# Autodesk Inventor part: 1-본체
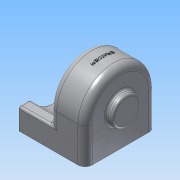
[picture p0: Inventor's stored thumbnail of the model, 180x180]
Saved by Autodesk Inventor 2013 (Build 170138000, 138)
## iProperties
Created: 2015-02
Part Number: 1-본체
Material: 알루미늄 6061
Document SubType Name: Modeling
Designer: Administrator
Density: 2.71 g/cm^3
Mass: 575.526 g
Surface Area: 706.56 cm^2
Volume: 212.371 cm^3
Author: Administrator
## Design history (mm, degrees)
sketch "스케치1"
  geometry: L1 (0, 0)-(50, 0); L2 (50, 0)-(50, 100); L3 (50, 100)-(0, 100); L4 (0, 100)-(0, 0)
  constraints: 8 end point, 2 parallel, 1 horizontal, 1 perpendicular
  dimensions: "d0" = 50 distance of L2.end L3.end; "d2" = 100 distance of L1.end L2.end
extrude "돌출1" new body sketch "스케치1" distance "d3" = 100; taper "d4" = 0 deg
fillet "모깎기1" dims "d5" = 50
fillet "모깎기2" dims "d6" = 10
feature "쉘1" dims "d7" = 4
node "작업 평면2"
sketch "스케치5"
  geometry: L1 (-80, 0)-(0, 0) reference; L2 (-5.359, 30)-(10, 30); L3 (10, 30)-(10, 0); L4 (-90, 50)-(-90, 0) reference; L5 (-80, 0)-(-90, 0) reference; L6 (10, 0)-(0, 0) reference; L7 (-74.641, 30)-(-90, 30); A1 r 40 centre (-40, 50) between (-5.359, 30) and (-74.641, 30); 1 further point
  constraints: 6 end point, 2 parallel, 2 point on circle, 1 centre point, 1 collinear, 1 midpoint, 1 perpendicular, 1 point on line, 1 vertical alignment
  dimensions: "d16" = 40 radius of A1; "d19" = 50 distance from line of L1 A1.centre; "d20" = 30 distance between parallel lines of L6 L2
extrude "돌출3" join sketch "스케치5" stored distance "d21" = 49; taper "d22" = 0 deg
sketch "스케치6"
  geometry: C1 r 25 at (0, 0); A1 r 40 centre (0, 0) between (0, -40) and (0, 40) reference; 1 further point
  constraints: 1 centre point, 1 coincident
  dimensions: "d23" = 50 diameter of C1
extrude "돌출4" join sketch "스케치6" distance "d25" = 10; taper "d26" = -20 deg
sketch "스케치7"
  geometry: C1 r 20 at (0, 0); A1 r 40 centre (0, 0) between (0, 40) and (0, -40) reference; 1 further point
  constraints: 1 centre point, 1 coincident
  dimensions: "d27" = 40 diameter of C1
extrude "돌출5" join sketch "스케치7" distance "d29" = 9; taper "d30" = 0 deg
hole "구멍1" diameter "d33" = 20; stored, may be unused: countersink angle "d37" = 90 deg, drill point angle "d39" = 0 deg; dims "d31" = 10, "d32" = 10, "d34" = 6, "d35" = 28, "d36" = 10, "d38" = 14
hole "구멍2" diameter "d42" = 20; stored, may be unused: countersink angle "d46" = 90 deg, drill point angle "d48" = 0 deg; dims "d40" = 10, "d41" = 10, "d43" = 6, "d44" = 28, "d45" = 8, "d47" = 10
sketch "스케치8"
  geometry: C1 r 14 at (0, 0) reference; C2 r 21.36 at (0, 0) reference; A1 r 18 centre (0, 0) between (-18, 0) and (18, 0); 3 further points
  constraints: 4 point on circle, 2 horizontal alignment, 2 vertical alignment, 1 centre point, 1 coincident
  dimensions: "d49" = 36 diameter of A1
hole "구멍3" sketch "스케치8" at (-18, 0), (18, 0), (0, 18), (0, -18) diameter "d51" = 2.459; stored, may be unused: countersink angle "d55" = 90 deg, drill point angle "d57" = 118 deg; dims "d52" = 6, "d53" = 28, "d54" = 8, "d56" = 9
sketch "스케치9"
  geometry: L1 (45, 100)-(45, 0) reference; L2 (3, 91.75)-(36, 91.75); L3 (36, 91.75)-(36, 8.25); L4 (36, 8.25)-(3, 8.25); L5 (3, 8.25)-(3, 91.75); 7 further points
  constraints: 8 end point, 4 coincident, 2 midpoint, 2 parallel, 1 horizontal, 1 horizontal alignment, 1 perpendicular
  dimensions: "d58" = 33 distance of L2.start L2.end; "d60" = 83.5 distance of L2.end L3.end; "d61" = 9 distance between parallel lines of L3 L1
hole "구멍4" sketch "스케치9" at (3, 91.75), (36, 91.75), (3, 8.25), (36, 8.25) diameter "d62" = 5.134; stored, may be unused: countersink angle "d66" = 90 deg, drill point angle "d68" = 118 deg; dims "d63" = 10, "d64" = 28, "d65" = 8, "d67" = 13
chamfer "모따기1" distance "d69" = 1; stored, may be unused: second distance "d70" = 2, angle "d71" = 45 deg
fillet "모깎기3" dims "d72" = 3, "d73" = 0.3
node "작업 평면3"
sketch "스케치10"
  geometry: L1 (46.5, 17)-(46.5, -17) reference; L2 (37.5, 40)-(37.5, -40) reference; 3 further points
  constraints: 1 horizontal alignment, 1 midpoint, 1 other
  dimensions: "d76" = 25 distance from line of L2 point (12.5, 0)
feature "엠보싱1" sketch "스케치10" dims "d0" = 50, "d2" = 100, "d16" = 40, "d19" = 50, "d20" = 30, "d77" = 0.5, "d78" = 0
node "솔리드1"
other parameters: "d15" = -95
